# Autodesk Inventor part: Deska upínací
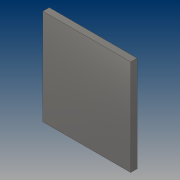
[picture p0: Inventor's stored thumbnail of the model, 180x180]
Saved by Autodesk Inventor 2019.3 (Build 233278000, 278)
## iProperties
Created: 2019-03
Part Number: Deska upínací
Material: Ocel, legovaná
Document SubType Name: Modeling
Designer: B-hon
Density: 7.73 g/cm^3
Appearance: Pololeštěná
Author: B-hon
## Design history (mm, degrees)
sketch "Náčrt1"
  geometry: L1 (0, 0)-(110, 0); L2 (110, 0)-(110, 120); L3 (110, 120)-(0, 120); L4 (0, 120)-(0, 0)
  constraints: 8 end point, 2 parallel, 1 horizontal, 1 perpendicular
  dimensions: "d11" = 110 distance of L3.end L2.end; "d12" = 120 distance of L2.end L1.end
extrude "Vysunutí2" new body sketch "Náčrt1" distance "d13" = 8; taper "d14" = 0 deg
node "Těleso2"
other parameters: "d3" = 30 deg
